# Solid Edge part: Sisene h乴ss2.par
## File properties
Author: Türk
Template: Iso Part.par
Last saved by: Türk
Revision: 13
Application: Solid Edge
Accuracy: 0,990
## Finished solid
Body 1: sheet body, 2 faces, 20 edges, 20 vertices.
  Faces by surface: plane 2
  Edges by curve: line 20
Body 2: solid body, 10 faces, 10 edges, 0 vertices.
  Faces by surface: cylinder 4, plane 4, cone 2
  Edges by curve: circle 10
Bounding box of the edges (mm): 50.000 x 50.000 x 50.000, from (-25, 0, -25) to (25, 50, 25).
Cylindrical faces by radius (mm): R20 x1, R22.5 x1, R25 x2
Conical faces (half-angle, radius in mm at the cone's reference point): 45 deg R20 x1, 45 deg R21 x1
Planar faces by outward normal: +y 2, -y 2
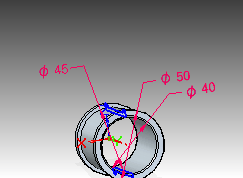
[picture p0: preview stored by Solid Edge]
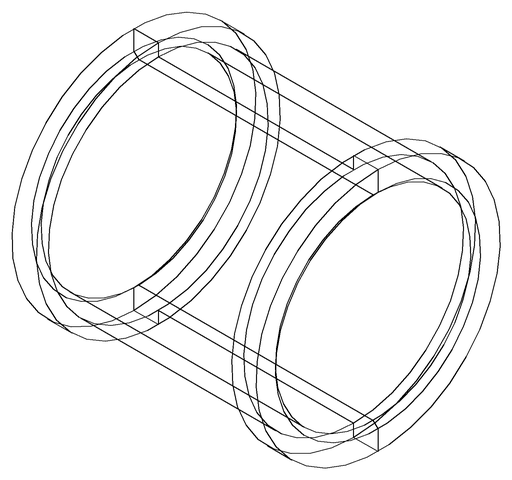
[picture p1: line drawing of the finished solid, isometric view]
